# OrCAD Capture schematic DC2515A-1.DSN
size C; title: 6 CELL MULTI-CHANNEL BATTERY MONITOR; rev: 1; company: TM
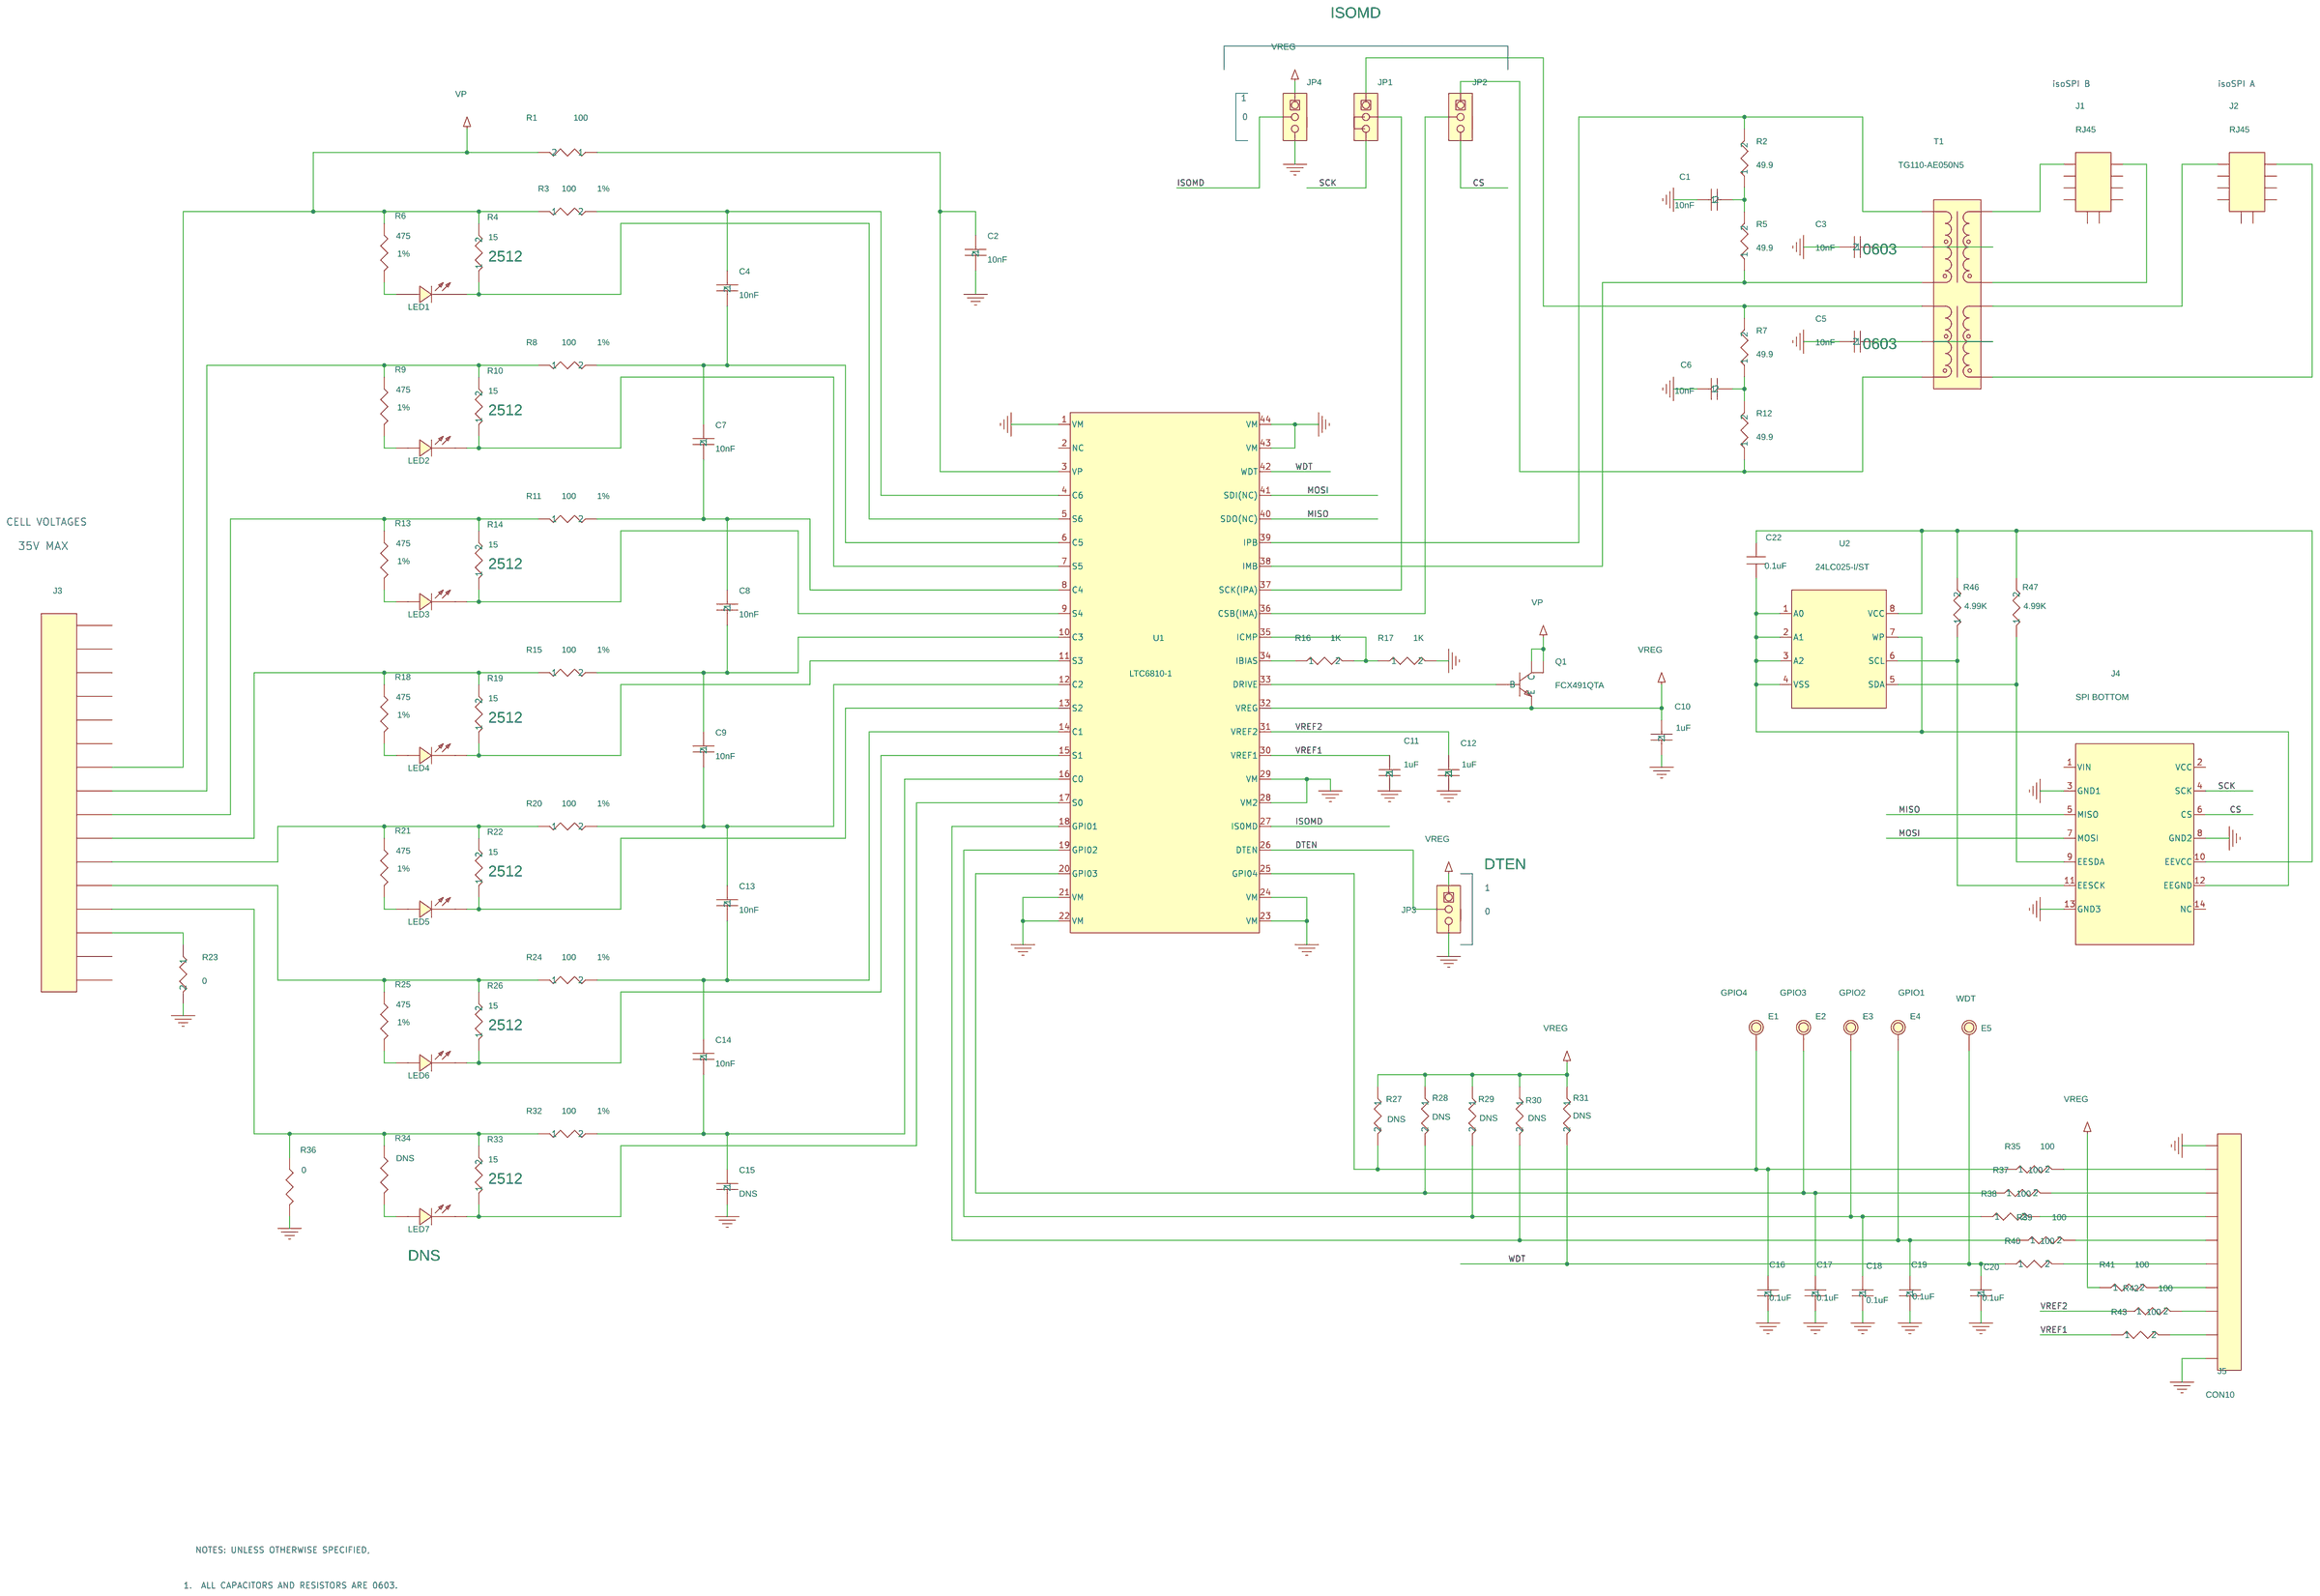
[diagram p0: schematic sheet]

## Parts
C1  10nF  [0603]
C2  10nF  [0603]
C3  10nF  [0603]
C4  10nF  [0603]
C5  10nF  [0603]
C6  10nF  [0603]
C7  10nF  [0603]
C8  10nF  [0603]
C9  10nF  [0603]
C10  1uF  [C0603]
C11  1uF  [C0603]
C12  1uF  [C0603]
C13  10nF  [0603]
C14  10nF  [0603]
C15  DNS  [C0603]
C16  0.1uF  [C0603]
C17  0.1uF  [C0603]
C18  0.1uF  [C0603]
C19  0.1uF  [C0603]
C20  0.1uF  [C0603]
C22  0.1uF  [C0603]
E1  GPIO4  [MILLMAX-2308-2]
E2  GPIO3  [MILLMAX-2308-2]
E3  GPIO2  [MILLMAX-2308-2]
E4  GPIO1  [MILLMAX-2308-2]
E5  WDT  [MILLMAX-2308-2]
J1  RJ45  [RJ45]
J2  RJ45  [RJ45]
J3  HEADER 16  [CONN\WDMLLR\176168200]
J4  SPI BOTTOM  [HD2X7-079-MOLEX]
J5  CON10  [HDR10X1PTH100]
JP1  JMP1X3  [JUMPER3\2MM]
JP2  JMP1X3  [JUMPER3\2MM]
JP3  JMP1X3  [JUMPER3\2MM]
JP4  JMP1X3  [JUMPER3\2MM]
LED1  LED  [LED\LTST-C190KGKT]
LED2  LED  [LED\LTST-C190KGKT]
LED3  LED  [LED\LTST-C190KGKT]
LED4  LED  [LED\LTST-C190KGKT]
LED5  LED  [LED\LTST-C190KGKT]
LED6  LED  [LED\LTST-C190KGKT]
LED7  LED  [LED\LTST-C190KGKT]
Q1  FCX491QTA  [SOT89]
R1  100  [0603]
R2  49.9  [R0603]
R3  100  [0603]
R4  15  [2512]
R5  49.9  [R0603]
R6  475  [R0603]
R7  49.9  [R0603]
R8  100  [0603]
R9  475  [R0603]
R10  15  [2512]
R11  100  [0603]
R12  49.9  [R0603]
R13  475  [R0603]
R14  15  [2512]
R15  100  [0603]
R16  1K  [0603]
R17  1K  [0603]
R18  475  [R0603]
R19  15  [2512]
R20  100  [0603]
R21  475  [R0603]
R22  15  [2512]
R23  0  [0603]
R24  100  [0603]
R25  475  [R0603]
R26  15  [2512]
R27  DNS  [0603]
R28  DNS  [0603]
R29  DNS  [0603]
R30  DNS  [0603]
R31  DNS  [0603]
R32  100  [0603]
R33  15  [2512]
R34  DNS  [R0603]
R35  100  [0603]
R36  0  [R0603]
R37  100  [0603]
R38  100  [0603]
R39  100  [0603]
R40  100  [0603]
R41  100  [0603]
R42  100  [0603]
R43  100  [0603]
R46  4.99K  [R0603]
R47  4.99K  [R0603]
T1  TG110-AE050N5  [TRAN-EPF8119S]
U1  LTC6810-1  [LTC-SSOP44-5.3MM]
U2  24LC025-I/ST  [ST-4.4MMTSSOP]
XJP1  2mm Ctrs.
XJP2  2mm Ctrs.
XJP3  2mm Ctrs.
XJP4  2mm Ctrs.

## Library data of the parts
C1 = CAP_NP_1_9: CAP, 0603 100nF 10% 25V X7R; Part Number: MURATA GCM188R71E104KA57D
C2 = CAP_NP_1_4: CAP, 0603 100nF 10% 25V X7R; Part Number: MURATA GCM188R71E104KA57D
C3 = CAP_NP_1_5: CAP, 0805 100nF 20% 100V X7R; Part Number: MURATA GCM21BR72A104KA37
C4 = CAP_NP_1_12: CAP, 0603 100nF 10% 25V X7R; Part Number: MURATA GCM188R71E104KA57D
C5 = CAP_NP_1_6: CAP, 0805 100nF 20% 100V X7R; Part Number: MURATA GCM21BR72A104KA37
C6 = CAP_NP_1_16: CAP, 0603 100nF 10% 25V X7R; Part Number: MURATA GCM188R71E104KA57D
C7 = CAP_NP_1_11: CAP, 0603 100nF 10% 25V X7R; Part Number: MURATA GCM188R71E104KA57D
C8 = CAP_NP_1: CAP, 0603 100nF 10% 25V X7R; Part Number: MURATA GCM188R71E104KA57D
C9 = CAP_NP_1_8: CAP, 0603 100nF 10% 25V X7R; Part Number: MURATA GCM188R71E104KA57D
C10 = CAP_NP_1_3: CAP, 0603 100nF 10% 25V X7R; Part Number: MURATA GCM188R71E104KA57D
C11 = CAP_NP_1_19: CAP, 0603 100nF 10% 25V X7R; Part Number: MURATA GCM188R71E104KA57D
C12 = CAP_NP_1_13: CAP, 0603 100nF 10% 25V X7R; Part Number: MURATA GCM188R71E104KA57D
C13 = CAP_NP_1_15: CAP, 0603 100nF 10% 25V X7R; Part Number: MURATA GCM188R71E104KA57D
C14 = CAP_NP_1_1: CAP, 0603 100nF 10% 25V X7R; Part Number: MURATA GCM188R71E104KA57D
C15 = CAP_NP_1_10: CAP, 0603 100nF 10% 25V X7R; Part Number: MURATA GCM188R71E104KA57D
C16 = CAP_NP_1_17: CAP, 0603 100nF 10% 25V X7R; Part Number: MURATA GCM188R71E104KA57D
C17 = CAP_NP_1_18: CAP, 0603 100nF 10% 25V X7R; Part Number: MURATA GCM188R71E104KA57D
C18 = CAP_NP_1_14: CAP, 0603 100nF 10% 25V X7R; Part Number: MURATA GCM188R71E104KA57D
C19 = CAP_NP_1_7: CAP, 0603 100nF 10% 25V X7R; Part Number: MURATA GCM188R71E104KA57D
C20 = CAP_NP_1_2: CAP, 0603 100nF 10% 25V X7R; Part Number: MURATA GCM188R71E104KA57D
C22 = CAP0603: CAP, 0603 100nF 10% 25V X7R; Part Number: MURATA GCM188R71E104KA57D; Voltage: 25V
E1-E5 = CON_KEY_575-4: 5th Part Field: 3V to 3.6V
J1 = HEADER_16_7
J2 = HEADER_16_8
J3 = HEADER_16_1: HEADER, 1X16 3.5mm, HORIZ.; Part Number: WEIDMULLER 1761682001
J4 = HEADER_7X2_8
J5 = CON10_0
JP1 = JMP1X3_2: HEADER,3PIN, 2mm; 1: ISOMD; Part Number: SAMTEC TMM-103-02-L-S
JP2 JP4 = JMP1X3_2: HEADER,3PIN, 2mm; Part Number: SAMTEC TMM-103-02-L-S
JP3 = JMP1X3_2: HEADER,3PIN, 2mm; 1: DTEN; Part Number: SAMTEC TMM-103-02-L-S
LED1-LED6 = LED_2: LED, 0603 GREEN; Part Number: LITE-ON LTST-C190KGKT
LED7 = LED_2: LED, 0603 GREEN; 1: DNS; Part Number: LITE-ON LTST-C190KGKT
Q1 = 2N1069_3
R1 = R_30: RES, 0603 100 OHMS 1% 1/10W; Part Number: NIC NRC06F1000TRF; Tol: 1%
R2 = R_17: RES, 0603 100 OHMS 1% 1/10W; Part Number: NIC NRC06F1000TRF; Tol: 1%
R3 = R_16: RES, 0603 100 OHMS 1% 1/10W; Part Number: NIC NRC06F1000TRF; Tol: 1%
R4 = R_28: RES, 0603 100 OHMS 1% 1/10W; Part Number: NIC NRC06F1000TRF; Tol: 1%
R5 = R_25: RES, 0603 100 OHMS 1% 1/10W; Part Number: NIC NRC06F1000TRF; Tol: 1%
R6 R9 R13 R18 R21 R25 R34 R36 = AAC-0603: RES, 0603 475 OHMS 1% 1/10W; Part Number: NIC NRC06F4750TRF; Tol: 1%
R7 = R_34: RES, 0603 100 OHMS 1% 1/10W; Part Number: NIC NRC06F1000TRF; Tol: 1%
R8 = R_19: RES, 0603 100 OHMS 1% 1/10W; Part Number: NIC NRC06F1000TRF; Tol: 1%
R10 = R_2: RES, 0603 100 OHMS 1% 1/10W; Part Number: NIC NRC06F1000TRF; Tol: 1%
R11 = R_36: RES, 0603 100 OHMS 1% 1/10W; Part Number: NIC NRC06F1000TRF; Tol: 1%
R12 = R_8: RES, 0603 100 OHMS 1% 1/10W; Part Number: NIC NRC06F1000TRF; Tol: 1%
R14 = R_20: RES, 0603 100 OHMS 1% 1/10W; Part Number: NIC NRC06F1000TRF; Tol: 1%
R15 = R_10: RES, 0603 100 OHMS 1% 1/10W; Part Number: NIC NRC06F1000TRF; Tol: 1%
R16 = R_31: RES, 0603 4.99K OHMS  1% 1/10W; 5%: 1%; Part Number: NIC NRC06F4991TRF; Tol: 1%
R17 = R_14: RES, 0603 4.99K OHMS  1% 1/10W; 5%: 1%; Part Number: NIC NRC06F4991TRF; Tol: 1%
R19 = R_32: RES, 0603 100 OHMS 1% 1/10W; Part Number: NIC NRC06F1000TRF; Tol: 1%
R20 = R_23: RES, 0603 100 OHMS 1% 1/10W; Part Number: NIC NRC06F1000TRF; Tol: 1%
R22 = R_9: RES, 0603 100 OHMS 1% 1/10W; Part Number: NIC NRC06F1000TRF; Tol: 1%
R23 = R_1: RES, 0603 4.99K OHMS  1% 1/10W; 5%: 1%; Part Number: NIC NRC06F4991TRF; Tol: 1%
R24 = R: RES, 0603 100 OHMS 1% 1/10W; Part Number: NIC NRC06F1000TRF; Tol: 1%
R26 = R_22: RES, 0603 100 OHMS 1% 1/10W; Part Number: NIC NRC06F1000TRF; Tol: 1%
R27 = R_27: RES, 0603 4.99K OHMS  1% 1/10W; 5%: 1%; Part Number: NIC NRC06F4991TRF; Tol: 1%
R28 = R_21: RES, 0603 4.99K OHMS  1% 1/10W; 5%: 1%; Part Number: NIC NRC06F4991TRF; Tol: 1%
R29 = R_12: RES, 0603 4.99K OHMS  1% 1/10W; 5%: 1%; Part Number: NIC NRC06F4991TRF; Tol: 1%
R30 = R_6: RES, 0603 4.99K OHMS  1% 1/10W; 5%: 1%; Part Number: NIC NRC06F4991TRF; Tol: 1%
R31 = R_3: RES, 0603 4.99K OHMS  1% 1/10W; 5%: 1%; Part Number: NIC NRC06F4991TRF; Tol: 1%
R32 = R_11: RES, 0603 100 OHMS 1% 1/10W; Part Number: NIC NRC06F1000TRF; Tol: 1%
R33 = R_35: RES, 0603 100 OHMS 1% 1/10W; Part Number: NIC NRC06F1000TRF; Tol: 1%
R35 = R_15: RES, 0603 4.99K OHMS  1% 1/10W; 5%: 1%; Part Number: NIC NRC06F4991TRF; Tol: 1%
R37 = R_24: RES, 0603 4.99K OHMS  1% 1/10W; 5%: 1%; Part Number: NIC NRC06F4991TRF; Tol: 1%
R38 = R_29: RES, 0603 4.99K OHMS  1% 1/10W; 5%: 1%; Part Number: NIC NRC06F4991TRF; Tol: 1%
R39 = R_5: RES, 0603 4.99K OHMS  1% 1/10W; 5%: 1%; Part Number: NIC NRC06F4991TRF; Tol: 1%
R40 = R_18: RES, 0603 4.99K OHMS  1% 1/10W; 5%: 1%; Part Number: NIC NRC06F4991TRF; Tol: 1%
R41 = R_13: RES, 0603 4.99K OHMS  1% 1/10W; 5%: 1%; Part Number: NIC NRC06F4991TRF; Tol: 1%
R42 = R_7: RES, 0603 4.99K OHMS  1% 1/10W; 5%: 1%; Part Number: NIC NRC06F4991TRF; Tol: 1%
R43 = R_33: RES, 0603 4.99K OHMS  1% 1/10W; 5%: 1%; Part Number: NIC NRC06F4991TRF; Tol: 1%
R46 = R_4: RES, 0603 100 OHMS 1% 1/10W; Part Number: NIC NRC06F1000TRF; Tol: 1%
R47 = R_26: RES, 0603 100 OHMS 1% 1/10W; Part Number: NIC NRC06F1000TRF; Tol: 1%
T1 = TRANS-PA0950_8: 4TH PART FIELD: PULSE,; 5TH PART FIELD: PA08xx; 7TH PART FIELD: TRANS.,
U1 = LTC6810_1
U2 = 24LC025_0: IC, 24LC025-I/ST; Part Number: MICROCHIP TECH. 24LC025-I/ST
XJP1-XJP4 = Samtec_2SN-BK-G_1

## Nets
GND: C1.1 C2.2 C3.2 C5.2 C6.1 C10.2 C11.2 C12.2 C15.2 C16.2 C17.2 C18.2 C19.2 C20.2 J4.3(GND1) J4.8(GND2) J4.13(GND3) J5.1 J5.10 JP3.3 JP4.3 R17.2 R23.2 R36.2 U1.1(VM) U1.21(VM) U1.22(VM) U1.23(VM) U1.24(VM) U1.28(VM2) U1.29(VM) U1.43(VM) U1.44(VM)
CS: J4.6(CS) JP2.3
DTEN: JP3.2 U1.26(DTEN)
ISOMD: JP4.2 U1.27(IS0MD)
MISO: J4.5(MISO) U1.40(SDO(NC))
MOSI: J4.7(MOSI) U1.41(SDI(NC))
SCK: J4.4(SCK) JP1.3
VP: J3.10 Q1.2(C) Q1.4 R1.2 R3.1 R4.2 R6.1
VREF1: C11.1 R43.1 U1.30(VREF1)
VREF2: C12.1 R42.1 U1.31(VREF2)
VREG: C10.1 JP3.1 JP4.1 Q1.3(E) R27.1 R28.1 R29.1 R30.1 R31.1 R41.1 U1.32(VREG)
WDT: C20.1 E5.1 R31.2 R40.1 U1.42(WDT)
N27955028: LED1.1(CATHODE) R4.1 U1.5(S6)
N27955056: C4.1 R3.2 U1.4(C6)
N27955860: J3.3 R23.1
N27957794: LED1.2(ANODE) R6.2
N27958585: J3.9 R8.1 R9.1 R10.2
N27958589: LED2.1(CATHODE) R10.1 U1.7(S5)
N27958593: C4.2 C7.1 R8.2 U1.6(C5)
N27958646: LED2.2(ANODE) R9.2
N27958797: J3.8 R11.1 R13.1 R14.2
N27958801: LED3.1(CATHODE) R14.1 U1.9(S4)
N27958805: C7.2 C8.1 R11.2 U1.8(C4)
N27958858: LED3.2(ANODE) R13.2
N27958956: J3.7 R15.1 R18.1 R19.2
N27958960: LED4.1(CATHODE) R19.1 U1.11(S3)
N27958964: C8.2 C9.1 R15.2 U1.10(C3)
N27959017: LED4.2(ANODE) R18.2
N27959115: J3.6 R20.1 R21.1 R22.2
N27959119: LED5.1(CATHODE) R22.1 U1.13(S2)
N27959123: C9.2 C13.1 R20.2 U1.12(C2)
N27959176: LED5.2(ANODE) R21.2
N27959274: J3.5 R24.1 R25.1 R26.2
N27959278: LED6.1(CATHODE) R26.1 U1.15(S1)
N27959282: C13.2 C14.1 R24.2 U1.14(C1)
N27959335: LED6.2(ANODE) R25.2
N27959433: J3.4 R32.1 R33.2 R34.1 R36.1
N27959437: LED7.1(CATHODE) R33.1 U1.17(S0)
N27959441: C14.2 C15.1 R32.2 U1.16(C0)
N27959494: LED7.2(ANODE) R34.2
N27960396: C19.1 E4.1 R30.2 R39.1 U1.18(GPI01)
N27960408: C18.1 E3.1 R29.2 R38.1 U1.19(GPI02)
N27960420: C17.1 E2.1 R28.2 R37.1 U1.20(GPI03)
N27961691: C16.1 E1.1 R27.2 R35.1 U1.25(GPI04)
N27962529: J5.5 R40.2
N27962613: J5.9 R35.2
N27962616: J5.8 R37.2
N27962619: J5.7 R38.2
N27962622: J5.6 R39.2
N27963063: J5.4 R41.2
N27963066: J5.3 R42.2
N27963069: J5.2 R43.2
N27963893: JP1.1 R7.2 T1.6
N27963906: R2.2 T1.1 U1.39(IPB)
N27963912: J1.2 T1.16
N27963916: R5.1 T1.3 U1.38(IMB)
N27963970: J2.2 T1.11
N27964006: C3.1 T1.2
N27964008: J1.1 T1.14
N27964014: C5.1 T1.7
N27964041: J2.1 T1.9
N27964748: Q1.1(B) U1.33(DRIVE)
N27965868: R16.1 U1.34(IBIAS)
N27965871: R16.2 R17.1 U1.35(ICMP)
N27967471: C1.2 R2.1 R5.2
N27967484: C6.2 R7.1 R12.2
N27967487: JP2.1 R12.1 T1.8
N27968605: JP1.2 U1.37(SCK(IPA))
N27968614: JP2.2 U1.36(CSB(IMA))
N27976502: C2.1 R1.1 U1.3(VP)
N27981430: J4.9(EESDA) R47.1 U2.5(SDA)
N27981432: C22.1 J4.10(EEVCC) R46.2 R47.2 U2.8(VCC)
N27981436: C22.2 J4.12(EEGND) U2.1(A0) U2.2(A1) U2.3(A2) U2.4(VSS) U2.7(WP)
N27981448: J4.11(EESCK) R46.1 U2.6(SCL)

Not connected (* = marked no-connect by the designer): J1 3 4 5 6 7 8 11 12; J2 3 4 5 6 7 8 11 12; J3 1 2 11 12 13 14 15 16; J4 1(VIN) 2(VCC) 14(NC); T1 10 15; U1 2(NC)

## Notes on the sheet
- isoSPI B
- isoSPI A
- 1
- 0
- CELL VOLTAGES
- 35V MAX
- 1
- 0
- NOTES: UNLESS OTHERWISE SPECIFIED,
- 1.  ALL CAPACITORS AND RESISTORS ARE 0603.
